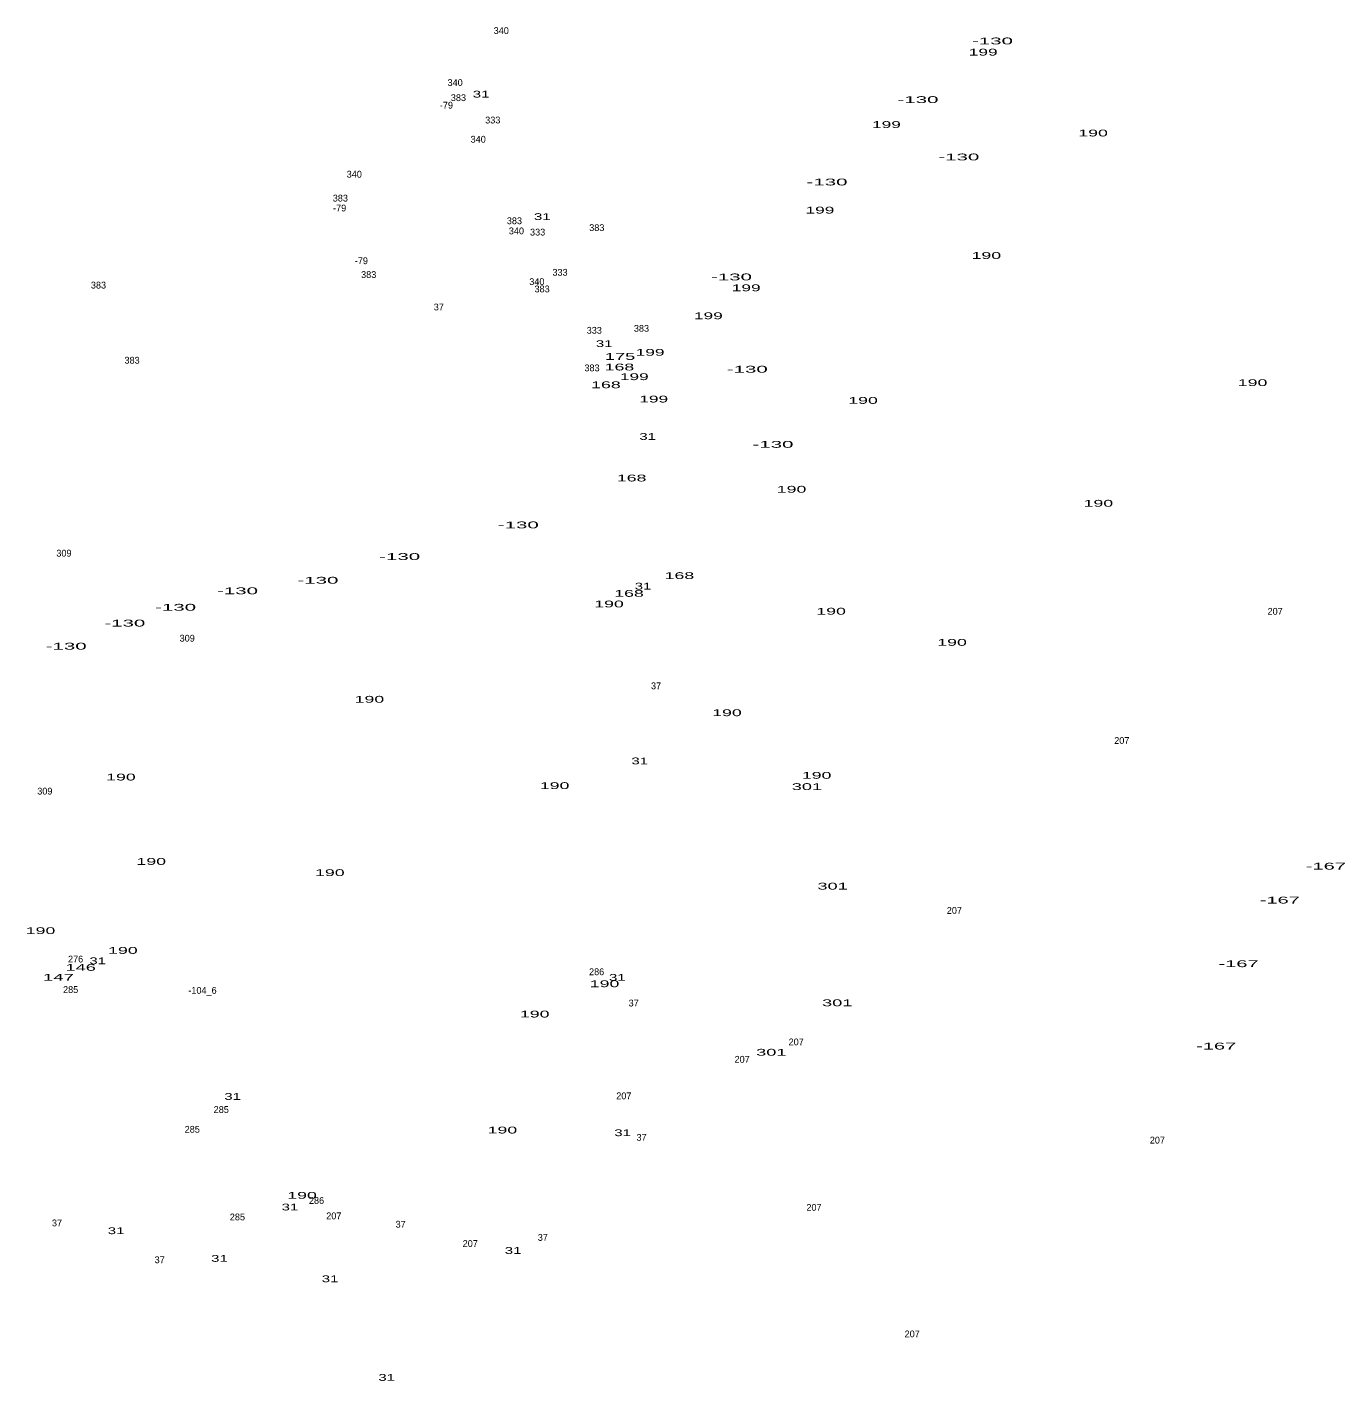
# Model space of a CAD drawing. Extents: x -662499 to -659675, y -1001682 to -998165.
# Drawn here: x -660461 to -659686, y -999142 to -998346 of the extents above; entities that cross this region are included whole.
import ezdxf
from ezdxf.enums import TextEntityAlignment as Align

# ---------------------------------------------------------------- set-up
doc = ezdxf.new("R2010")
doc.units = 0
doc.header["$LTSCALE"] = 1.6
doc.layers.add('24', color=7, linetype='Continuous')

msp = doc.modelspace()

# ---------------------------------------------------------------- texts
at = {"layer": '24'}
for s, p in [('340', (-660182.505, -998349.77)), ('340', (-660209.645, -998380.38)), ('383', (-660207.707, -998389.26)), ('-79', (-660214.775, -998393.67)), ('333', (-660187.487, -998402.42)), ('340', (-660196.075, -998413.73)), ('340', (-660268.965, -998434.29)), ('383', (-660277.167, -998448.36)), ('-79', (-660277.585, -998454.18)), ('383', (-660174.767, -998461.7)), ('340', (-660173.585, -998467.65)), ('333', (-660161.117, -998468.36)), ('383', (-660126.297, -998465.73)), ('-79', (-660264.795, -998485.21)), ('383', (-660260.487, -998493.35)), ('333', (-660147.937, -998492.02)), ('383', (-660419.457, -998499.55)), ('340', (-660161.565, -998497.51)), ('383', (-660158.477, -998501.8)), ('37', (-660219.243, -998512.44)), ('333', (-660127.777, -998526.15)), ('383', (-660100.027, -998524.99)), ('383', (-660399.687, -998543.77)), ('383', (-660129.107, -998548.27)), ('309', (-660439.777, -998657.3)), ('207', (-659727.237, -998691.51)), ('309', (-660367.267, -998707.34)), ('37', (-660091.443, -998735.37)), ('207', (-659817.457, -998767.53)), ('309', (-660451.017, -998797.33)), ('207', (-659915.947, -998867.53)), ('276', (-660432.918, -998896.15)), ('286', (-660126.403, -998903.62)), ('285', (-660435.827, -998914.09)), ('-104_6', (-660358.27, -998914.56)), ('37', (-660104.613, -998922.03)), ('207', (-660009.007, -998944.9)), ('207', (-660040.797, -998955.14)), ('207', (-660110.397, -998976.65)), ('285', (-660347.227, -998984.69)), ('285', (-660364.287, -998996.33)), ('37', (-660099.963, -999001.06)), ('207', (-659796.527, -999002.7)), ('286', (-660291.193, -999038.21)), ('207', (-659998.537, -999042.26)), ('37', (-660443.863, -999051.42)), ('285', (-660337.727, -999047.91)), ('207', (-660280.997, -999047.25)), ('37', (-660241.703, -999052.19)), ('37', (-660158.053, -999059.94)), ('207', (-660200.737, -999063.54)), ('37', (-660383.443, -999073.11)), ('207', (-659940.767, -999116.73))]:
    msp.add_text(s, height=4, dxfattribs=at).set_placement(p, align=Align.CENTER)
for s, width, p in [('-130', 2.25, (-659893.547, -998355.88)), ('199', 1.9, (-659898.987, -998362.46)), ('31', 1.65, (-660194.377, -998387.17)), ('-130', 2.25, (-659937.357, -998390.4)), ('199', 1.9, (-659955.917, -998405.07)), ('190', 1.95, (-659834.339, -998410.06)), ('-130', 2.25, (-659913.317, -998424.15)), ('-130', 2.25, (-659990.867, -998438.89)), ('31', 1.65, (-660158.367, -998459.23)), ('199', 1.9, (-659995.037, -998455.44)), ('190', 1.95, (-659897.149, -998482.13)), ('-130', 2.25, (-660047.087, -998494.74)), ('199', 1.9, (-660038.407, -998501.15)), ('199', 1.9, (-660060.677, -998517.61)), ('31', 1.65, (-660121.957, -998534)), ('175', 2, (-660112.623, -998541.53)), ('199', 1.9, (-660094.947, -998539.11)), ('168', 1.95, (-660112.983, -998547.76)), ('-130', 2.25, (-660037.787, -998549.05)), ('168', 1.95, (-660120.933, -998558.21)), ('199', 1.9, (-660104.247, -998553.45)), ('190', 1.95, (-659740.509, -998556.96)), ('199', 1.9, (-660092.817, -998566.62)), ('190', 1.95, (-659969.659, -998567.41)), ('31', 1.65, (-660096.397, -998588.62)), ('-130', 2.25, (-660022.657, -998593.26)), ('168', 1.95, (-660105.813, -998613.09)), ('190', 1.95, (-660011.729, -998619.7)), ('190', 1.95, (-659831.239, -998627.94)), ('-130', 2.25, (-660172.487, -998640.66)), ('-130', 2.25, (-660242.277, -998659.28)), ('-130', 2.25, (-660290.357, -998673.24)), ('31', 1.65, (-660099.107, -998676.69)), ('168', 1.95, (-660077.703, -998670.5)), ('-130', 2.25, (-660337.657, -998679.45)), ('168', 1.95, (-660107.363, -998680.97)), ('-130', 2.25, (-660374.107, -998689.14)), ('190', 1.95, (-660119.129, -998687.19)), ('190', 1.95, (-659988.459, -998691.46)), ('-130', 2.25, (-660403.957, -998698.45)), ('-130', 2.25, (-660438.467, -998712.03)), ('190', 1.95, (-659917.309, -998709.78)), ('190', 1.95, (-660260.069, -998743.28)), ('190', 1.95, (-660049.729, -998751.19)), ('31', 1.65, (-660101.047, -998779.54)), ('190', 1.95, (-660406.249, -998789.05)), ('190', 1.95, (-659996.989, -998788.04)), ('190', 1.95, (-660151.119, -998794.09)), ('301', 2, (-660002.704, -998794.67)), ('190', 1.95, (-660388.409, -998838.7)), ('-167', 2.2, (-659697.379, -998841.47)), ('190', 1.95, (-660283.339, -998845.29)), ('301', 2, (-659987.584, -998853.24)), ('-167', 2.2, (-659724.519, -998861.45)), ('190', 1.95, (-660453.549, -998879.43)), ('190', 1.95, (-660405.089, -998891.06)), ('31', 1.65, (-660419.927, -998897.18)), ('-167', 2.2, (-659748.749, -998898.88)), ('147', 2.05, (-660442.998, -998906.86)), ('146', 2, (-660429.928, -998901.06)), ('31', 1.65, (-660114.217, -998906.92)), ('190', 1.95, (-660121.729, -998910.68)), ('301', 2, (-659984.864, -998921.89)), ('190', 1.95, (-660162.829, -998928.52)), ('-167', 2.2, (-659761.939, -998947.36)), ('301', 2, (-660023.644, -998950.99)), ('31', 1.65, (-660340.537, -998976.98)), ('190', 1.95, (-660181.829, -998996.78)), ('31', 1.65, (-660111.117, -998998.35)), ('190', 1.95, (-660299.699, -999035.18)), ('31', 1.65, (-660306.837, -999042.07)), ('31', 1.65, (-660409.077, -999056.01)), ('31', 1.65, (-660175.557, -999067.64)), ('31', 1.65, (-660348.277, -999072.29)), ('31', 1.65, (-660283.217, -999084.3)), ('31', 1.65, (-660249.907, -999142.33))]:
    msp.add_text(s, height=4, dxfattribs=dict(at, width=width)).set_placement(p, align=Align.CENTER)

doc.saveas('drawing.dxf')
